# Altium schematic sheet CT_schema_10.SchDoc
size 387 x 278 mm
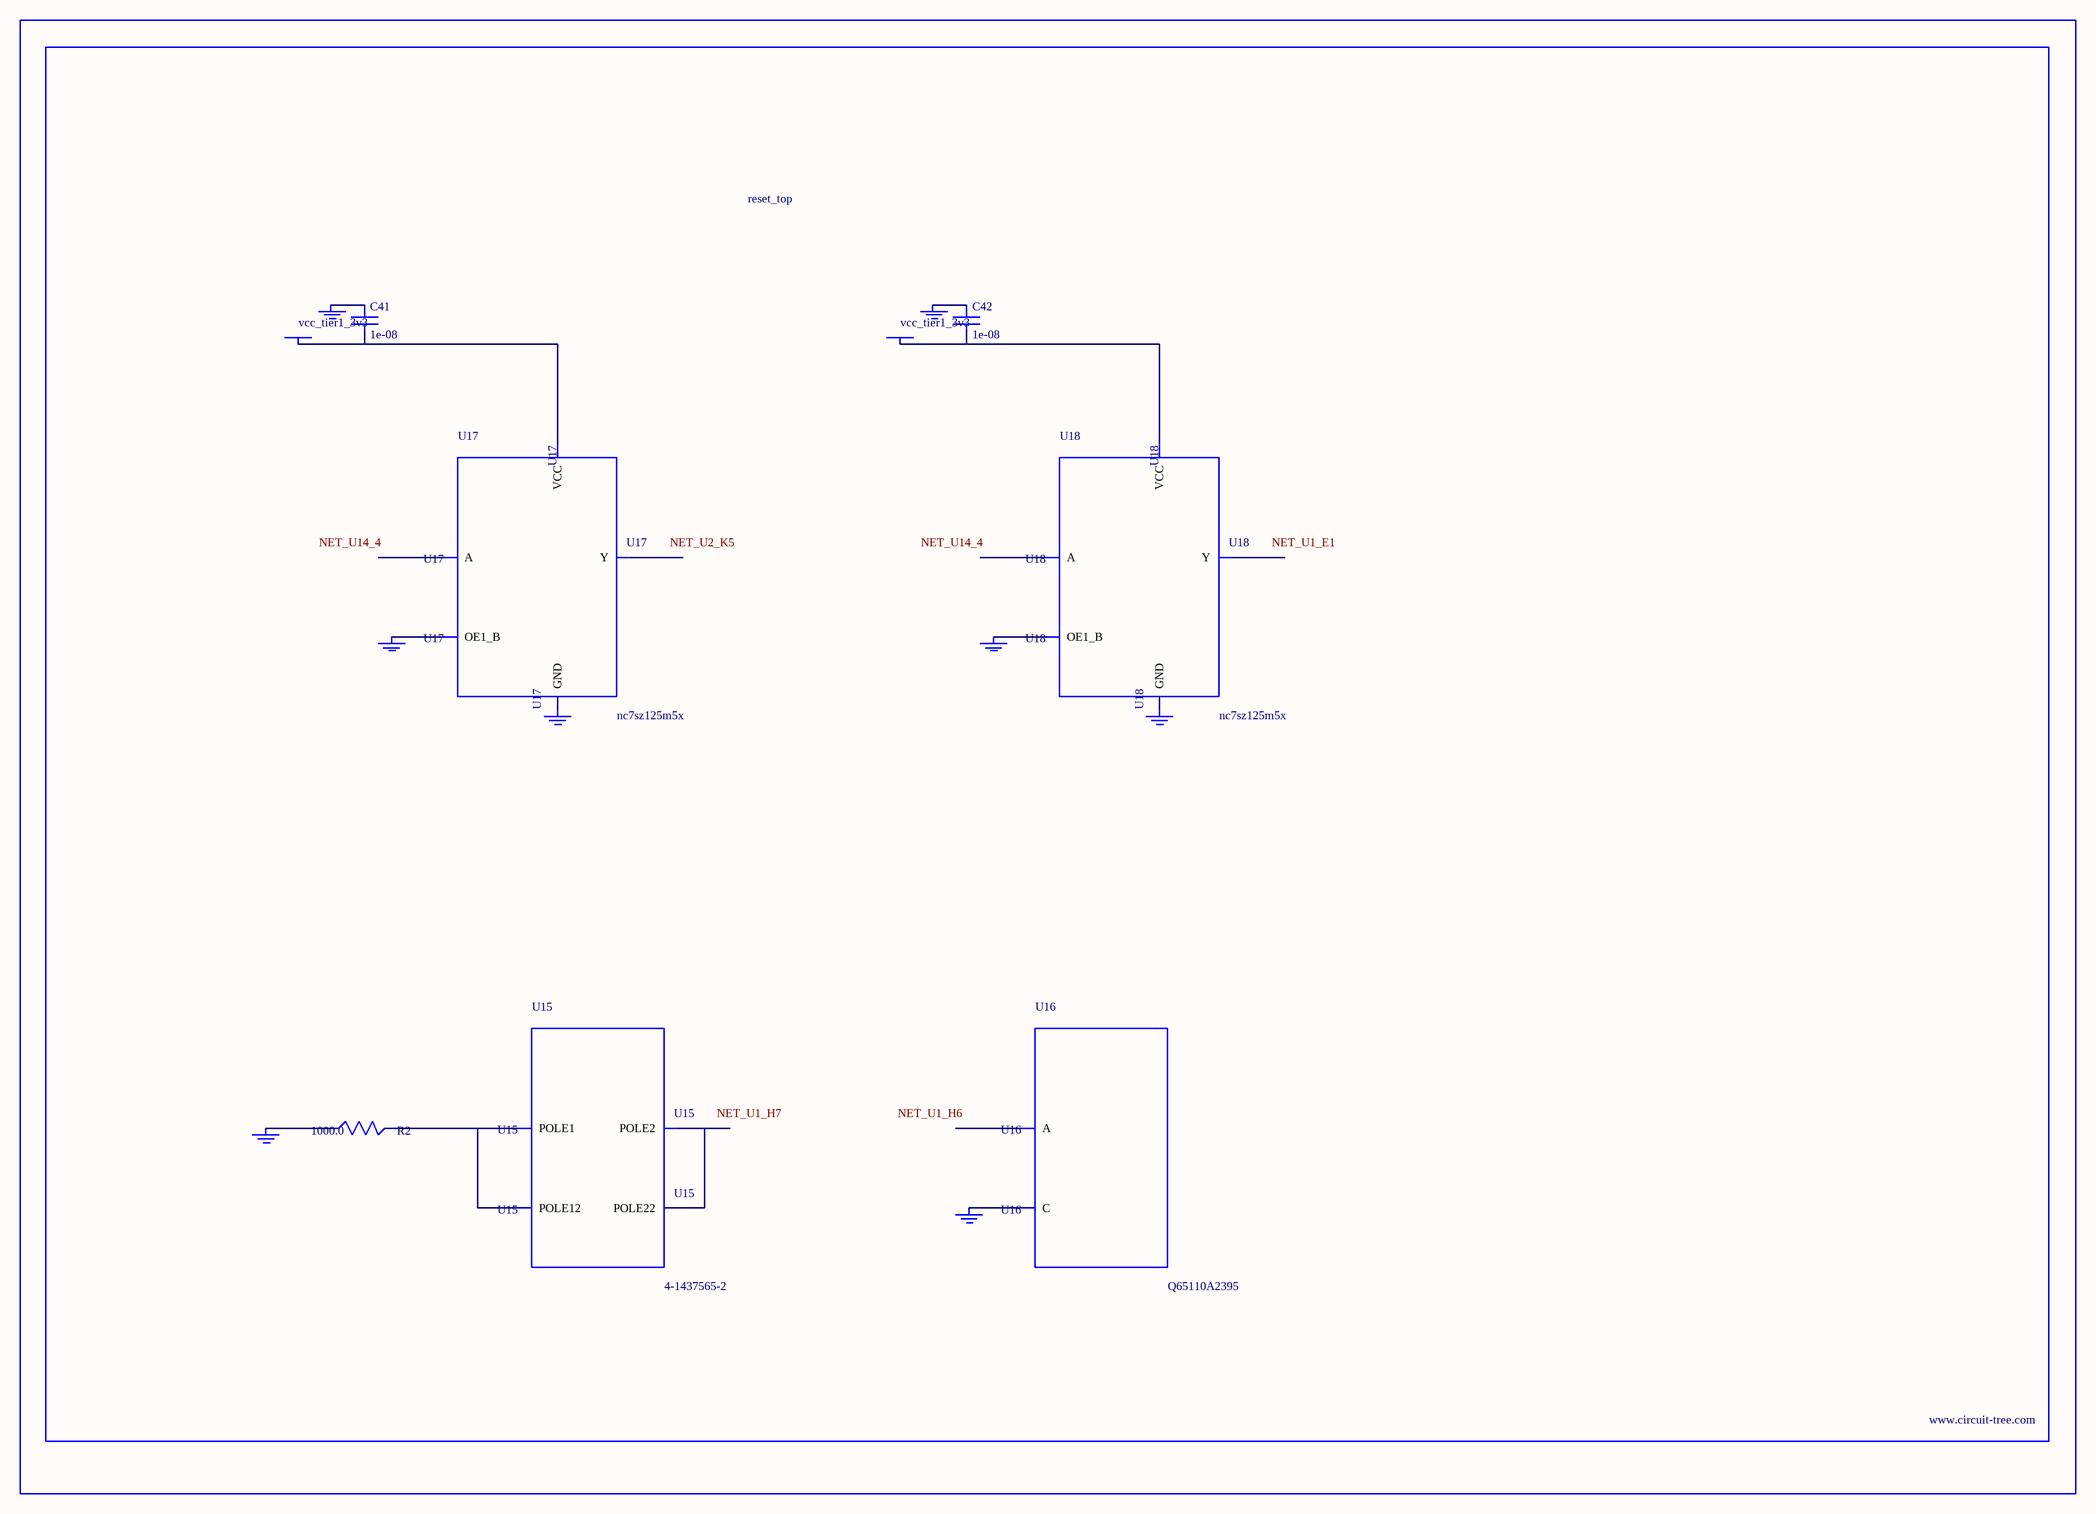
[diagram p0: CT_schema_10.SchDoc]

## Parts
BORDER9  (no value)
C41  1e-08  [C0402]
C42  1e-08  [C0402]
GND_INSTANCE_9_0  (no value)
GND_INSTANCE_9_1  (no value)
GND_INSTANCE_9_2  (no value)
GND_INSTANCE_9_3  (no value)
GND_INSTANCE_9_4  (no value)
GND_INSTANCE_9_5  (no value)
GND_INSTANCE_9_6  (no value)
GND_INSTANCE_9_7  (no value)
POWER_INSTANCE_9_0  vcc_tier1_3v3
POWER_INSTANCE_9_1  vcc_tier1_3v3
R2  1000.0  [R0603]
U15  4-1437565-2  [SW_4-1437565-2]
U16  Q65110A2395  [LGM67K-G1J2-24-Z]
U17  nc7sz125m5x  [NC7SZ125M5X]
U18  nc7sz125m5x  [NC7SZ125M5X]

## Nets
NetC41_1: C41.1 GND_INSTANCE_9_2.0(GND)
NetC41_2: C41.2 POWER_INSTANCE_9_0.0(PWR) U17.5(VCC)
NetC42_1: C42.1 GND_INSTANCE_9_5.0(GND)
NetC42_2: C42.2 POWER_INSTANCE_9_1.0(PWR) U18.5(VCC)
NetGND_INSTANCE_9_0_0: GND_INSTANCE_9_0.0(GND) R2.1
NetGND_INSTANCE_9_1_0: GND_INSTANCE_9_1.0(GND) U16.C
NetGND_INSTANCE_9_3_0: GND_INSTANCE_9_3.0(GND) U17.1(OE1_B)
NetGND_INSTANCE_9_4_0: GND_INSTANCE_9_4.0(GND) U17.3(GND)
NetGND_INSTANCE_9_6_0: GND_INSTANCE_9_6.0(GND) U18.1(OE1_B)
NetGND_INSTANCE_9_7_0: GND_INSTANCE_9_7.0(GND) U18.3(GND)
NetR2_2: R2.2 U15.1(POLE1) U15.2(POLE12)
NetU15_3: U15.3(POLE2) U15.4(POLE22)

Not connected (* = marked no-connect by the designer): U16 A; U17 2(A) 4(Y); U18 2(A) 4(Y)

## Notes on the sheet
- Labels drawn without touching a wire or pin: NET_U1_E1, NET_U1_H6, NET_U1_H7, NET_U2_K5, NET_U14_4

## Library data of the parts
BORDER9 = BORDER_PAGE9
C41 C42 = C0402C103K3RAC
GND_INSTANCE_9_0-GND_INSTANCE_9_7 = GND
POWER_INSTANCE_9_0 POWER_INSTANCE_9_1 = PWR
R2 = RC0603JR-071KL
